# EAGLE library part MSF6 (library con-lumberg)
MSF CONNECTOR
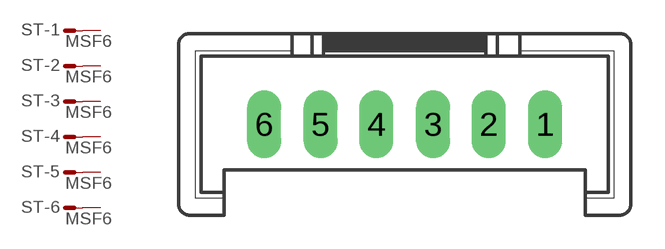
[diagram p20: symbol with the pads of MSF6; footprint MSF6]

Designator prefix ST; gates -1=M -2=M -3=M -4=M -5=M -6=M

## MSF6 (OC_FARNELL: unknown; OC_NEWARK: unknown)  [MSF6]
1  -1:S  pas
2  -2:S  pas
3  -3:S  pas
4  -4:S  pas
5  -5:S  pas
6  -6:S  pas

## Footprint MSF6 (pad centres in mm)
MSF CONNECTOR Buerklin Nr. 56 F 561
drill 1.016 long: 1 6.274,-2.54; 2 3.759,-2.54; 3 1.27,-2.54; 4 -1.27,-2.54; 5 -3.759,-2.54; 6 -6.274,-2.54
